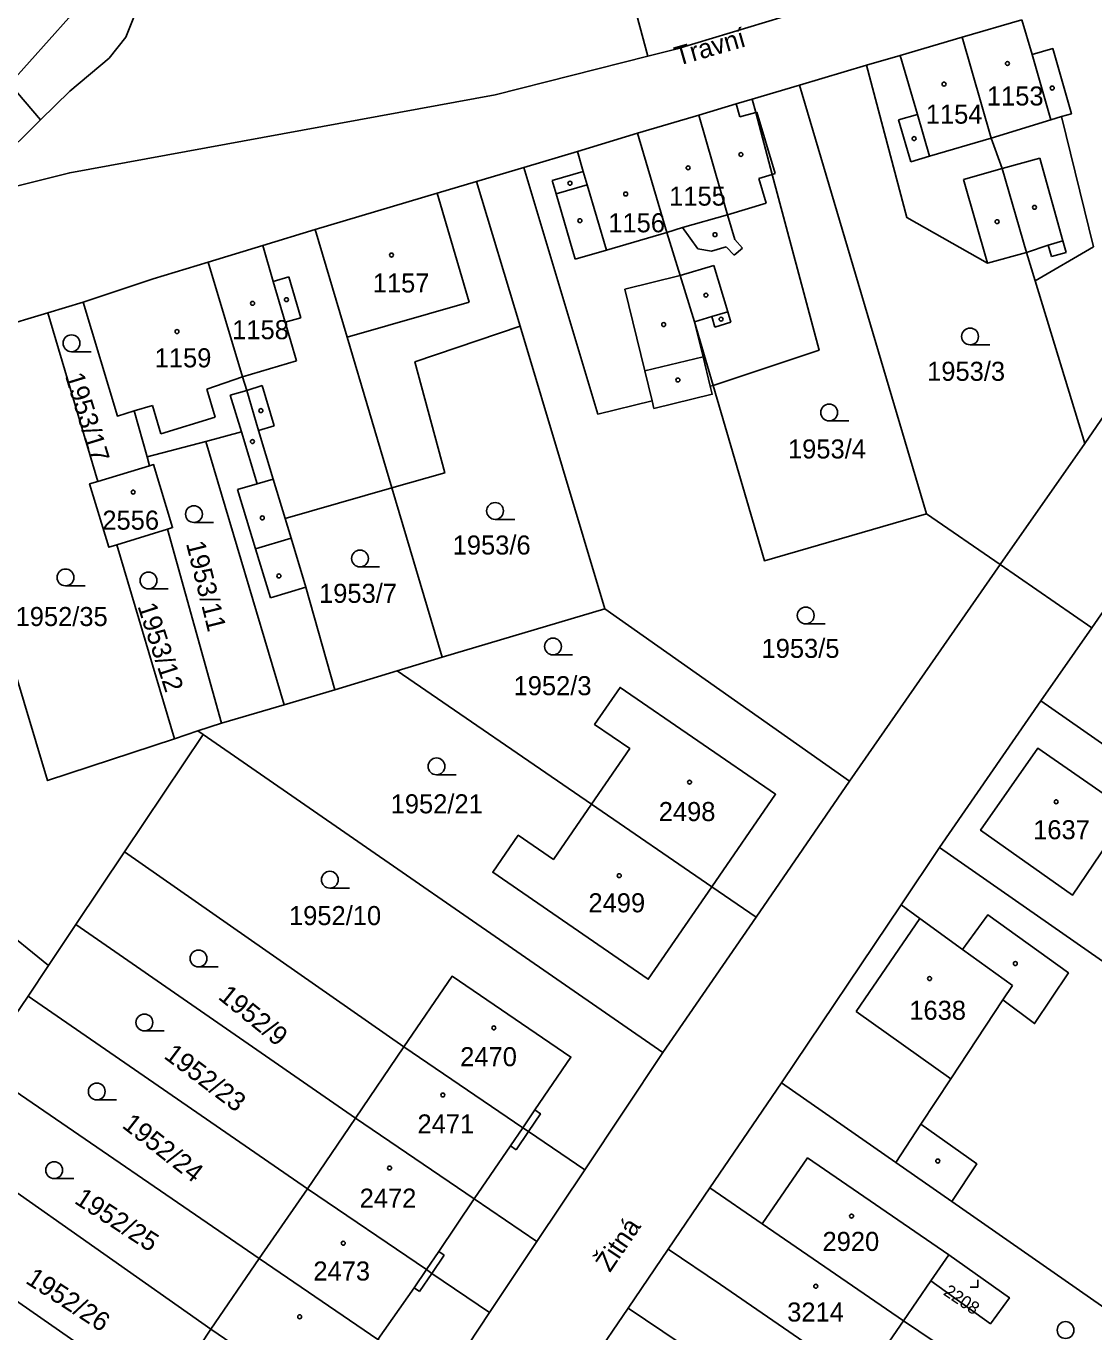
# Model space of a CAD drawing. Extents: x -679220 to -673243, y -1075091 to -1066557.
# Drawn here: x -676648.8 to -676553.6, y -1072700.8 to -1072584.3 of the extents above; entities that cross this region are included whole.
import ezdxf

# ---------------------------------------------------------------- set-up
doc = ezdxf.new("R2010")
doc.units = 0
for name, color, linetype in [('Hranice parcel', 7, 'Continuous'), ('Parcelní čísla', 7, 'Continuous'), ('Pop  PČ popisy', 7, 'Continuous'), ('Vnitřní kresba', 7, 'Continuous'), ('Značky budov', 7, 'Continuous'), ('Značky kultur', 7, 'Continuous')]:
    doc.layers.add(name, color=color, linetype=linetype)

msp = doc.modelspace()

# ---------------------------------------------------------------- linework, layer by layer
at = {"layer": 'Hranice parcel'}
for p, q in [((-676597.58, -1072571.22), (-676593.34, -1072586.97)), ((-676565.31, -1072585.26), (-676559.98, -1072583.7)), ((-676579.83, -1072589.53), (-676573.85, -1072587.77)), ((-676650.25, -1072589.43), (-676647.52, -1072592.64)), ((-676584.05, -1072590.79), (-676579.83, -1072589.53)), ((-676579.83, -1072589.53), (-676568.49, -1072627.8)), ((-676652.34, -1072597.37), (-676647.52, -1072592.64)), ((-676608.64, -1072598.13), (-676604.42, -1072596.88)), ((-676604.75, -1072611.05), (-676608.64, -1072598.13)), ((-676559.57, -1072604.47), (-676558.8, -1072606.99)), ((-676543.64, -1072605.83), (-676554.38, -1072621.51)), ((-676554.38, -1072621.51), (-676558.8, -1072606.99)), ((-676643.72, -1072608.9), (-676646.88, -1072609.85)), ((-676646.88, -1072609.85), (-676658.37, -1072613.31)), ((-676642.41, -1072624.9), (-676646.88, -1072609.85)), ((-676604.75, -1072611.05), (-676597.18, -1072636.25)), ((-676561.93, -1072632.31), (-676554.38, -1072621.51)), ((-676637.79, -1072623.5), (-676638.01, -1072622.71)), ((-676642.41, -1072624.9), (-676637.79, -1072623.5)), ((-676625.7, -1072628.21), (-676616.18, -1072625.47)), ((-676616.18, -1072625.47), (-676611.69, -1072640.58)), ((-676568.49, -1072627.8), (-676561.93, -1072632.31)), ((-676636.21, -1072629.16), (-676640.72, -1072630.55)), ((-676631.37, -1072646.47), (-676636.21, -1072629.16)), ((-676548.06, -1072629.7), (-676553.76, -1072637.97)), ((-676635.58, -1072647.85), (-676640.72, -1072630.55)), ((-676561.93, -1072632.31), (-676575.35, -1072651.65)), ((-676553.76, -1072637.97), (-676561.93, -1072632.31)), ((-676597.18, -1072636.25), (-676611.69, -1072640.58)), ((-676575.35, -1072651.65), (-676597.18, -1072636.25)), ((-676553.76, -1072637.97), (-676558.31, -1072644.47)), ((-676611.69, -1072640.58), (-676615.7, -1072641.79)), ((-676615.7, -1072641.79), (-676621.28, -1072643.48)), ((-676598.38, -1072653.69), (-676615.7, -1072641.79)), ((-676621.28, -1072643.48), (-676625.79, -1072644.82)), ((-676625.79, -1072644.82), (-676631.37, -1072646.47)), ((-676558.31, -1072644.47), (-676567.35, -1072657.57)), ((-676544.7, -1072653.95), (-676558.31, -1072644.47)), ((-676633.02, -1072647.47), (-676640.03, -1072657.95)), ((-676633.48, -1072647.16), (-676635.58, -1072647.85)), ((-676631.37, -1072646.47), (-676633.48, -1072647.16)), ((-676633.48, -1072647.16), (-676633.02, -1072647.47)), ((-676592, -1072675.85), (-676633.02, -1072647.47)), ((-676575.35, -1072651.65), (-676583.7, -1072663.78)), ((-676598.38, -1072653.69), (-676587.64, -1072661.07)), ((-676640.03, -1072657.95), (-676644.37, -1072664.44)), ((-676615.11, -1072675.35), (-676640.03, -1072657.95)), ((-676567.35, -1072657.57), (-676570.77, -1072662.67)), ((-676655.85, -1072660.75), (-676646.81, -1072668.09)), ((-676583.7, -1072663.78), (-676587.64, -1072661.07)), ((-676592, -1072675.85), (-676583.7, -1072663.78)), ((-676570.77, -1072662.67), (-676581.42, -1072678.54)), ((-676644.37, -1072664.44), (-676646.81, -1072668.09)), ((-676644.37, -1072664.44), (-676619.43, -1072681.7)), ((-676646.81, -1072668.09), (-676648.64, -1072670.81)), ((-676648.64, -1072670.81), (-676651.01, -1072674.34)), ((-676648.64, -1072670.81), (-676623.72, -1072688)), ((-676619.43, -1072681.7), (-676615.11, -1072675.35)), ((-676598.98, -1072686.32), (-676592, -1072675.85)), ((-676650.84, -1072678.59), (-676628.01, -1072694.22)), ((-676581.42, -1072678.54), (-676587.81, -1072687.92)), ((-676623.72, -1072688), (-676619.43, -1072681.7)), ((-676632.33, -1072700.52), (-676657.14, -1072683.09)), ((-676604.01, -1072682.9), (-676598.98, -1072686.32)), ((-676603.24, -1072692.71), (-676598.98, -1072686.32)), ((-676628.01, -1072694.22), (-676623.72, -1072688)), ((-676587.81, -1072687.92), (-676591.54, -1072693.39)), ((-676587.81, -1072687.92), (-676583.14, -1072691.13)), ((-676566.25, -1072689.13), (-676545.05, -1072703.94)), ((-676661.64, -1072689.7), (-676636.67, -1072707.03)), ((-676583.14, -1072691.13), (-676570.56, -1072699.78)), ((-676607.47, -1072699.05), (-676603.24, -1072692.71)), ((-676591.54, -1072693.39), (-676595.12, -1072698.65)), ((-676566.51, -1072693.9), (-676568.11, -1072696.22)), ((-676628.01, -1072694.22), (-676632.33, -1072700.52)), ((-676568.11, -1072696.22), (-676570.56, -1072699.78)), ((-676598.77, -1072704), (-676595.12, -1072698.65)), ((-676611.7, -1072705.39), (-676607.47, -1072699.05)), ((-676570.56, -1072699.78), (-676574.29, -1072705.21)), ((-676570.56, -1072699.78), (-676551.56, -1072712.54)), ((-676636.67, -1072707.03), (-676632.33, -1072700.52))]:
    msp.add_line(p, q, dxfattribs=at)
for points in [[(-676600.72, -1072503.07), (-676606.15, -1072509.65), (-676615.52, -1072525.52), (-676623.12, -1072540.2), (-676630.2, -1072558.24), (-676644.99, -1072583.54), (-676650.25, -1072589.43)], [(-676647.52, -1072592.64), (-676644.91, -1072590.08), (-676641.41, -1072587.12), (-676639.91, -1072585.27), (-676637.38, -1072578.92), (-676629.15, -1072564.42), (-676622.89, -1072551.66), (-676618.62, -1072544.59), (-676613.89, -1072536.85), (-676606.32, -1072525.48), (-676604.84, -1072521.96)], [(-676546.35, -1072572.11), (-676556.24, -1072575.81), (-676568.92, -1072579.9), (-676581.29, -1072583.45), (-676590.74, -1072586.31), (-676593.34, -1072586.97)], [(-676558.8, -1072606.99), (-676553.61, -1072603.96), (-676556.45, -1072592.35), (-676555.57, -1072592.09), (-676557.24, -1072586.28), (-676559.08, -1072586.82), (-676559.98, -1072583.7)], [(-676573.85, -1072587.77), (-676570.84, -1072586.89), (-676565.31, -1072585.26)], [(-676565.31, -1072585.26), (-676562.74, -1072594.27), (-676561.74, -1072596.99), (-676559.57, -1072604.47)], [(-676593.34, -1072586.97), (-676606.98, -1072590.41), (-676644.92, -1072597.35), (-676654.89, -1072599.85)], [(-676573.85, -1072587.77), (-676570.24, -1072601.36), (-676563.04, -1072605.41), (-676559.57, -1072604.47)], [(-676594.27, -1072593.83), (-676588.81, -1072592.21), (-676585.46, -1072591.21), (-676584.05, -1072590.79)], [(-676587.52, -1072616.35), (-676578.07, -1072613.2), (-676582.26, -1072597.51), (-676583.73, -1072591.98), (-676584.05, -1072590.79)], [(-676604.42, -1072596.88), (-676599.63, -1072595.47), (-676594.27, -1072593.83)], [(-676594.27, -1072593.83), (-676591.66, -1072602.69), (-676590.46, -1072606.53), (-676589.18, -1072610.65), (-676587.52, -1072616.35)], [(-676604.42, -1072596.88), (-676597.8, -1072618.89), (-676592.98, -1072617.7), (-676592.81, -1072618.38), (-676587.61, -1072617.12), (-676587.78, -1072616.41), (-676587.52, -1072616.35)], [(-676623.02, -1072602.43), (-676612.13, -1072599.18), (-676608.64, -1072598.13)], [(-676632.58, -1072605.32), (-676627.7, -1072603.85), (-676623.02, -1072602.43)], [(-676623.02, -1072602.43), (-676620.17, -1072612.02), (-676616.18, -1072625.47)], [(-676643.72, -1072608.9), (-676637.48, -1072606.83), (-676632.58, -1072605.32)], [(-676632.58, -1072605.32), (-676629.5, -1072615.56), (-676629.13, -1072616.79), (-676628.07, -1072620.34), (-676626.76, -1072624.7), (-676625.7, -1072628.21)], [(-676638.01, -1072622.71), (-676639.16, -1072618.61), (-676640.66, -1072619.06), (-676643.72, -1072608.9)], [(-676616.18, -1072625.47), (-676611.47, -1072624.14), (-676614.13, -1072614.24), (-676604.75, -1072611.05)], [(-676658.37, -1072613.31), (-676646.9, -1072651.58), (-676635.58, -1072647.85)], [(-676587.52, -1072616.35), (-676582.95, -1072631.98), (-676568.49, -1072627.8)], [(-676638.01, -1072622.71), (-676632.79, -1072621.32), (-676625.79, -1072644.82)], [(-676636.21, -1072629.16), (-676635.75, -1072629.02), (-676637.44, -1072623.4), (-676637.79, -1072623.5)], [(-676640.72, -1072630.55), (-676641.44, -1072630.77), (-676643.15, -1072625.12), (-676642.41, -1072624.9)], [(-676621.28, -1072643.48), (-676623.87, -1072634.32), (-676625.18, -1072629.95), (-676625.7, -1072628.21)], [(-676587.64, -1072661.07), (-676581.96, -1072652.81), (-676595.83, -1072643.27), (-676598.11, -1072646.57), (-676594.97, -1072648.73), (-676598.38, -1072653.69)], [(-676550.42, -1072654.33), (-676558.56, -1072648.68), (-676563.67, -1072656.02), (-676555.46, -1072661.8), (-676550.42, -1072654.33)], [(-676587.64, -1072661.07), (-676593.31, -1072669.31), (-676607.18, -1072659.77), (-676604.91, -1072656.46), (-676601.77, -1072658.62), (-676598.38, -1072653.69)], [(-676529.98, -1072683.88), (-676534.32, -1072680.56), (-676567.35, -1072657.57)], [(-676566.25, -1072689.13), (-676564.02, -1072685.78), (-676568.99, -1072682.24), (-676566.33, -1072678.21), (-676561.68, -1072671.16), (-676558.85, -1072673.26), (-676555.83, -1072668.75), (-676563.02, -1072663.55), (-676565.27, -1072666.65), (-676569.09, -1072663.89), (-676570.77, -1072662.67)], [(-676615.11, -1072675.35), (-676610.82, -1072669.05), (-676600.22, -1072676.26), (-676603.43, -1072680.97), (-676602.93, -1072681.31), (-676604.01, -1072682.9)], [(-676615.11, -1072675.35), (-676604.51, -1072682.56), (-676604.01, -1072682.9)], [(-676581.42, -1072678.54), (-676571.23, -1072685.65), (-676566.25, -1072689.13)], [(-676619.43, -1072681.7), (-676608.83, -1072688.91), (-676603.24, -1072692.71)], [(-676583.14, -1072691.13), (-676579.1, -1072685.25), (-676566.51, -1072693.9)], [(-676623.72, -1072688), (-676613.11, -1072695.21), (-676612.62, -1072695.55), (-676607.47, -1072699.05)], [(-676574.29, -1072705.21), (-676586.88, -1072696.55), (-676591.54, -1072693.39)], [(-676568.11, -1072696.22), (-676562.8, -1072700.04), (-676561.1, -1072697.73), (-676566.51, -1072693.9)], [(-676628.01, -1072694.22), (-676617.44, -1072701.46), (-676611.7, -1072705.39)], [(-676595.12, -1072698.65), (-676590.47, -1072701.78), (-676577.88, -1072710.43)], [(-676632.33, -1072700.52), (-676621.76, -1072707.76), (-676621.26, -1072708.1), (-676616.12, -1072711.79)]]:
    msp.add_lwpolyline(points, dxfattribs=at)
at = {"layer": 'Vnitřní kresba'}
for p, q in [((-676570.84, -1072586.89), (-676569.31, -1072592.16)), ((-676557.4, -1072592.64), (-676559.08, -1072586.82)), ((-676585.46, -1072591.21), (-676585.16, -1072592.36)), ((-676586.24, -1072601.11), (-676588.81, -1072592.21)), ((-676585.16, -1072592.36), (-676583.73, -1072591.98)), ((-676583.73, -1072591.98), (-676583.63, -1072591.95)), ((-676583.63, -1072591.95), (-676581.98, -1072597.43)), ((-676569.31, -1072592.16), (-676571, -1072592.65)), ((-676571, -1072592.65), (-676569.9, -1072596.38)), ((-676568.22, -1072595.88), (-676569.31, -1072592.16)), ((-676562.74, -1072594.27), (-676557.4, -1072592.64)), ((-676557.4, -1072592.64), (-676556.45, -1072592.35)), ((-676568.22, -1072595.88), (-676562.74, -1072594.27)), ((-676599.63, -1072595.47), (-676599.11, -1072597.25)), ((-676569.9, -1072596.38), (-676568.22, -1072595.88)), ((-676561.74, -1072596.99), (-676558.4, -1072596.06)), ((-676558.4, -1072596.06), (-676556.33, -1072603.44)), ((-676599.11, -1072597.25), (-676601.88, -1072598.04)), ((-676598.76, -1072598.44), (-676599.11, -1072597.25)), ((-676565.2, -1072597.95), (-676561.74, -1072596.99)), ((-676601.88, -1072598.04), (-676601.53, -1072599.25)), ((-676601.53, -1072599.25), (-676598.76, -1072598.44)), ((-676597.05, -1072604.26), (-676598.76, -1072598.44)), ((-676583.46, -1072597.87), (-676582.26, -1072597.51)), ((-676583.46, -1072597.87), (-676582.8, -1072600.08)), ((-676582.26, -1072597.51), (-676581.98, -1072597.43)), ((-676563.04, -1072605.41), (-676565.2, -1072597.95)), ((-676609.29, -1072608.89), (-676612.13, -1072599.18)), ((-676601.53, -1072599.25), (-676599.83, -1072605.07)), ((-676582.8, -1072600.08), (-676586.24, -1072601.11)), ((-676586.24, -1072601.11), (-676590.27, -1072602.24)), ((-676585.58, -1072603.3), (-676586.24, -1072601.11)), ((-676597.05, -1072604.26), (-676591.66, -1072602.69)), ((-676590.27, -1072602.24), (-676591.66, -1072602.69)), ((-676590.27, -1072602.24), (-676588.89, -1072604.14)), ((-676626.76, -1072607.05), (-676627.7, -1072603.85)), ((-676599.83, -1072605.07), (-676597.05, -1072604.26)), ((-676588.89, -1072604.14), (-676587.67, -1072604.35)), ((-676587.67, -1072604.35), (-676586.38, -1072603.97)), ((-676586.38, -1072603.97), (-676585.66, -1072604.71)), ((-676585.66, -1072604.71), (-676584.92, -1072604.09)), ((-676584.92, -1072604.09), (-676585.58, -1072603.3)), ((-676557.64, -1072603.81), (-676559.57, -1072604.47)), ((-676557.64, -1072603.81), (-676556.33, -1072603.44)), ((-676557.35, -1072604.83), (-676557.64, -1072603.81)), ((-676556.33, -1072603.44), (-676556.04, -1072604.46)), ((-676556.04, -1072604.46), (-676557.35, -1072604.83)), ((-676625.38, -1072606.64), (-676626.76, -1072607.05)), ((-676624.31, -1072610.29), (-676625.38, -1072606.64)), ((-676590.46, -1072606.53), (-676595.4, -1072607.74)), ((-676590.46, -1072606.53), (-676587.47, -1072605.62)), ((-676587.47, -1072605.62), (-676586.22, -1072609.76)), ((-676626.76, -1072607.05), (-676625.7, -1072610.7)), ((-676595.4, -1072607.74), (-676593.63, -1072615.04)), ((-676620.17, -1072612.02), (-676609.29, -1072608.89)), ((-676587.65, -1072610.19), (-676589.18, -1072610.65)), ((-676587.65, -1072610.19), (-676586.22, -1072609.76)), ((-676587.37, -1072611.13), (-676587.65, -1072610.19)), ((-676586.22, -1072609.76), (-676585.94, -1072610.7)), ((-676625.7, -1072610.7), (-676624.31, -1072610.29)), ((-676624.69, -1072614.14), (-676625.7, -1072610.7)), ((-676588.42, -1072613.78), (-676589.18, -1072610.65)), ((-676585.94, -1072610.7), (-676587.37, -1072611.13)), ((-676629.5, -1072615.56), (-676624.69, -1072614.14)), ((-676593.63, -1072615.04), (-676588.42, -1072613.78)), ((-676588.42, -1072613.78), (-676587.78, -1072616.41)), ((-676632.7, -1072616.66), (-676629.5, -1072615.56)), ((-676593.63, -1072615.04), (-676592.98, -1072617.7)), ((-676632.7, -1072616.66), (-676631.94, -1072619.17)), ((-676630.6, -1072617.2), (-676629.13, -1072616.79)), ((-676629.61, -1072620.48), (-676630.6, -1072617.2)), ((-676627.76, -1072616.33), (-676629.13, -1072616.79)), ((-676626.68, -1072619.94), (-676627.76, -1072616.33)), ((-676639.16, -1072618.61), (-676637.55, -1072618.13)), ((-676636.79, -1072620.64), (-676637.55, -1072618.13)), ((-676631.94, -1072619.17), (-676636.79, -1072620.64)), ((-676629.61, -1072620.48), (-676632.79, -1072621.32)), ((-676628.21, -1072625.12), (-676629.61, -1072620.48)), ((-676628.07, -1072620.34), (-676626.68, -1072619.94)), ((-676629.96, -1072625.62), (-676628.21, -1072625.12)), ((-676628.21, -1072625.12), (-676626.76, -1072624.7)), ((-676628.35, -1072630.91), (-676629.96, -1072625.62)), ((-676628.35, -1072630.91), (-676625.18, -1072629.95)), ((-676627.02, -1072635.29), (-676628.35, -1072630.91)), ((-676623.87, -1072634.32), (-676627.02, -1072635.29)), ((-676574.77, -1072672.18), (-676569.09, -1072663.89)), ((-676565.27, -1072666.65), (-676560.83, -1072669.87)), ((-676560.83, -1072669.87), (-676561.68, -1072671.16)), ((-676574.77, -1072672.18), (-676566.33, -1072678.21)), ((-676604.51, -1072682.56), (-676603.43, -1072680.97)), ((-676568.99, -1072682.24), (-676571.23, -1072685.65)), ((-676605.61, -1072684.18), (-676604.51, -1072682.56)), ((-676604.01, -1072682.9), (-676605.11, -1072684.52)), ((-676608.83, -1072688.91), (-676605.61, -1072684.18)), ((-676605.11, -1072684.52), (-676605.61, -1072684.18)), ((-676612.01, -1072693.59), (-676608.83, -1072688.91)), ((-676612.01, -1072693.59), (-676613.11, -1072695.21)), ((-676612.62, -1072695.55), (-676611.51, -1072693.93)), ((-676611.51, -1072693.93), (-676612.01, -1072693.59)), ((-676613.11, -1072695.21), (-676614.21, -1072696.83)), ((-676613.72, -1072697.16), (-676612.62, -1072695.55)), ((-676617.44, -1072701.46), (-676614.21, -1072696.83)), ((-676614.21, -1072696.83), (-676613.72, -1072697.16))]:
    msp.add_line(p, q, dxfattribs=at)
at = {"layer": 'Značky budov'}
for centre in [(-676561.28, -1072587.61), (-676566.93, -1072589.45), (-676557.28, -1072589.8), (-676569.6, -1072594.31), (-676585.05, -1072595.73), (-676589.76, -1072596.92), (-676600.3, -1072598.29), (-676595.33, -1072599.25), (-676558.86, -1072600.44), (-676599.41, -1072601.63), (-676562.2, -1072601.72), (-676587.36, -1072602.88), (-676616.22, -1072604.7), (-676628.61, -1072609.01), (-676625.59, -1072608.68), (-676588.17, -1072608.28), (-676635.35, -1072611.53), (-676591.94, -1072610.9), (-676586.82, -1072610.42), (-676590.67, -1072615.85), (-676627.87, -1072618.58), (-676628.62, -1072621.34), (-676639.26, -1072625.85), (-676627.74, -1072628.15), (-676626.26, -1072633.33), (-676589.63, -1072651.73), (-676556.93, -1072653.48), (-676595.9, -1072660.07), (-676560.57, -1072667.91), (-676568.22, -1072669.25), (-676607.09, -1072673.65), (-676611.64, -1072679.64), (-676567.49, -1072685.53), (-676616.39, -1072686.15), (-676575.18, -1072690.44), (-676620.52, -1072692.86), (-676578.37, -1072696.7), (-676624.41, -1072699.42)]:
    msp.add_circle(centre, 0.175, dxfattribs=at)
at = {"layer": 'Značky kultur'}
for p, q in [((-676644.76, -1072613.32), (-676643.01, -1072613.32)), ((-676564.61, -1072612.71), (-676562.86, -1072612.71)), ((-676577.18, -1072619.5), (-676575.43, -1072619.5)), ((-676633.84, -1072628.56), (-676632.09, -1072628.56)), ((-676606.98, -1072628.28), (-676605.23, -1072628.28)), ((-676619.03, -1072632.52), (-676617.28, -1072632.52)), ((-676645.3, -1072634.21), (-676643.55, -1072634.21)), ((-676637.89, -1072634.48), (-676636.14, -1072634.48)), ((-676579.27, -1072637.61), (-676577.52, -1072637.61)), ((-676601.81, -1072640.38), (-676600.06, -1072640.38)), ((-676612.2, -1072651.07), (-676610.45, -1072651.07)), ((-676621.72, -1072661.18), (-676619.97, -1072661.18)), ((-676633.43, -1072668.21), (-676631.68, -1072668.21)), ((-676638.26, -1072673.92), (-676636.51, -1072673.92)), ((-676642.51, -1072680.07), (-676640.76, -1072680.07)), ((-676646.31, -1072687.1), (-676644.56, -1072687.1)), ((-676563.93, -1072696.79), (-676563.93, -1072696.12)), ((-676564.6, -1072696.79), (-676563.93, -1072696.79))]:
    msp.add_line(p, q, dxfattribs=at)
for centre in [(-676564.61, -1072611.96), (-676644.76, -1072612.57), (-676577.18, -1072618.75), (-676633.84, -1072627.81), (-676606.98, -1072627.53), (-676619.03, -1072631.77), (-676645.3, -1072633.46), (-676637.89, -1072633.73), (-676579.27, -1072636.86), (-676601.81, -1072639.63), (-676612.2, -1072650.32), (-676621.72, -1072660.43), (-676633.43, -1072667.46), (-676638.26, -1072673.17), (-676642.51, -1072679.32), (-676646.31, -1072686.35), (-676556.09, -1072700.61)]:
    msp.add_circle(centre, 0.75, dxfattribs=at)

# ---------------------------------------------------------------- texts
at = {"layer": 'Parcelní čísla'}
for s, p in [('1153', (-676563.11, -1072591.36)), ('1154', (-676568.56, -1072592.98)), ('1155', (-676591.45, -1072600.29)), ('1156', (-676596.88, -1072602.67)), ('1157', (-676617.89, -1072608.04)), ('1158', (-676630.43, -1072612.21)), ('1159', (-676637.34, -1072614.72)), ('1953/3', (-676568.44, -1072615.92)), ('1953/4', (-676580.85, -1072622.85)), ('2556', (-676642.01, -1072629.2)), ('1953/6', (-676610.76, -1072631.42)), ('1953/7', (-676622.68, -1072635.73)), ('1952/35', (-676649.75, -1072637.8)), ('1953/5', (-676583.21, -1072640.64)), ('1952/3', (-676605.33, -1072643.97)), ('1952/21', (-676616.29, -1072654.51)), ('2498', (-676592.38, -1072655.2)), ('1637', (-676558.98, -1072656.82)), ('2499', (-676598.65, -1072663.34)), ('1952/10', (-676625.36, -1072664.48)), ('1638', (-676570.03, -1072672.93)), ('2470', (-676610.09, -1072677.07)), ('2471', (-676613.9, -1072683.07)), ('2472', (-676619.06, -1072689.69)), ('2920', (-676577.77, -1072693.55)), ('2473', (-676623.19, -1072696.19)), ('3214', (-676580.92, -1072699.85))]:
    msp.add_text(s, height=1.7, dxfattribs=at).set_placement(p)
for s, height, rotation, p in [('1953/17', 1.7, 287, (-676645.35, -1072615.47)), ('1953/11', 1.7, 284, (-676634.56, -1072630.43)), ('1953/12', 1.7, 288, (-676638.89, -1072636.02)), ('1952/9', 1.7, 321, (-676631.77, -1072671)), ('1952/23', 1.7, 323, (-676636.61, -1072676.29)), ('1952/24', 1.7, 322, (-676640.34, -1072682.48)), ('1952/25', 1.7, 327, (-676644.6, -1072689.23)), ('1952/26', 1.7, 327, (-676648.95, -1072696.36)), ('2208', 1.139, 326, (-676567.07, -1072697.41))]:
    msp.add_text(s, height=height, rotation=rotation, dxfattribs=at).set_placement(p)
at = {"layer": 'Pop  PČ popisy'}
for s, rotation, p in [('Travní', 16, (-676590.68, -1072587.83)), ('Žitná', 56, (-676596.73, -1072695.53))]:
    msp.add_text(s, height=1.7, rotation=rotation, dxfattribs=at).set_placement(p)

doc.saveas('drawing.dxf')
